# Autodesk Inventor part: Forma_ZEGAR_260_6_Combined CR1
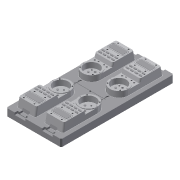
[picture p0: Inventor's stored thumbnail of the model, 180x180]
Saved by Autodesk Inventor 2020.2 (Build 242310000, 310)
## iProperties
Created: 2015-01
Part Number: Forma_ZEGAR_260_6_Combined CR1
Material: Ogólny
Document SubType Name: Modeling
Designer: F.Stasiak
Density: 1 g/cm^3
Appearance: Domyślna
Mass: 1377.71 g
Surface Area: 1826.06 cm^2
Volume: 1377.71 cm^3
Catalog Web Link: www.expertbooks.pl
Manager: www.cadconsulting.pl
Company: Fabian Stasiak CAD Consulting
Author: F.Stasiak
Subject: Zbiór ćwiczeń. Autodesk Inventor 2020. Kurs Professional
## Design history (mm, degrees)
node "Forma_ZEGAR_260_4_AsmContainer" dims "d0" = 10
sketch "Szkic1"
  geometry: L1 (0, 320)-(156, 320) reference; L2 (156, 320)-(156, 0) reference; L3 (156, 0)-(0, 0) reference; L4 (0, 0)-(0, 320) reference; L5 (0, 320)-(156, 320) reference; L6 (156, 320)-(156, 0) reference; L7 (156, 0)-(0, 0) reference; L8 (0, 0)-(0, 320) reference; L9 (0, 320)-(156, 320) reference; L10 (156, 320)-(156, 0) reference; L11 (156, 0)-(0, 0) reference; L12 (0, 0)-(0, 320) reference; L13 (0, 320)-(156, 320) reference; L14 (156, 320)-(156, 0) reference; L15 (156, 0)-(0, 0) reference; L16 (0, 0)-(0, 320) reference; L17 (156, 320)-(0, 320); L18 (0, 320)-(0, 0); L19 (0, 0)-(156, 0); L20 (156, 0)-(156, 320)
  constraints: 8 end point, 2 parallel, 1 horizontal, 1 perpendicular
sketch "Szkic2"
  geometry: L1 (78, 160)-(-78, 160) reference; L2 (-78, 160)-(-78, -160) reference; L3 (-78, -160)-(78, -160) reference; L4 (78, -160)-(78, 160) reference
sketch "Szkic3"
  geometry: L1 (78, 160)-(-78, 160) reference; L2 (-78, 160)-(-78, -160) reference; L3 (-78, -160)-(78, -160) reference; L4 (78, -160)-(78, 160) reference
sketch "Szkic4"
  geometry: L1 (78, 160)-(-78, 160) reference; L2 (-78, 160)-(-78, -160) reference; L3 (-78, -160)-(78, -160) reference; L4 (78, -160)-(78, 160) reference
sketch "Szkic5"
  geometry: L1 (78, 160)-(-78, 160) reference; L2 (-78, 160)-(-78, -160) reference; L3 (-78, -160)-(78, -160) reference; L4 (78, -160)-(78, 160) reference
chamfer "Faza1" distance "d1" = 3; stored, may be unused: second distance "d2" = 3, angle "d3" = 45 deg
chamfer "Faza2" distance "d4" = 3; stored, may be unused: second distance "d5" = 3, angle "d6" = 45 deg
chamfer "Faza3" distance "d7" = 3; stored, may be unused: second distance "d8" = 3, angle "d9" = 45 deg
chamfer "Faza4" distance "d10" = 3; stored, may be unused: second distance "d11" = 3, angle "d12" = 45 deg
sketch "Szkic6"
  geometry: 1 further point
hole "Otwór1" sketch "Szkic6" at (75, 160) diameter "d13" = 3.5; stored, may be unused: countersink angle "d17" = 90 deg, drill point angle "d19" = 0 deg; dims "d14" = 6, "d15" = 4, "d16" = 2, "d18" = 8
sketch "Szkic7"
  geometry: 1 further point
hole "Otwór2" sketch "Szkic7" at (21, 294) diameter "d20" = 4; stored, may be unused: countersink angle "d24" = 90 deg, drill point angle "d26" = 0 deg; dims "d21" = 6, "d22" = 4, "d23" = 2, "d25" = 8
feature "Rzeźbienie1"
sketch "Szkic8"
  geometry: 1 further point
hole "Otwór3" sketch "Szkic8" at (51, 294) diameter "d27" = 4; stored, may be unused: countersink angle "d31" = 90 deg, drill point angle "d33" = 0 deg; dims "d28" = 6, "d29" = 4, "d30" = 2, "d32" = 8
feature "Rzeźbienie2"
sketch "Szkic9"
  geometry: 1 further point
hole "Otwór4" sketch "Szkic9" at (21, 263.5) diameter "d34" = 4; stored, may be unused: countersink angle "d38" = 90 deg, drill point angle "d40" = 0 deg; dims "d35" = 6, "d36" = 4, "d37" = 2, "d39" = 8
feature "Rzeźbienie3"
sketch "Szkic10"
  geometry: 1 further point
hole "Otwór5" sketch "Szkic10" at (51, 263.5) diameter "d41" = 4; stored, may be unused: countersink angle "d45" = 90 deg, drill point angle "d47" = 0 deg; dims "d42" = 6, "d43" = 4, "d44" = 2, "d46" = 8
feature "Rzeźbienie4"
sketch "Szkic11"
  geometry: 1 further point
hole "Otwór6" sketch "Szkic11" at (28, 231.2) diameter "d48" = 4; stored, may be unused: countersink angle "d52" = 90 deg, drill point angle "d54" = 0 deg; dims "d49" = 6, "d50" = 4, "d51" = 2, "d53" = 8
feature "Rzeźbienie5"
sketch "Szkic12"
  geometry: 1 further point
hole "Otwór7" sketch "Szkic12" at (44, 231.2) diameter "d55" = 4; stored, may be unused: countersink angle "d59" = 90 deg, drill point angle "d61" = 0 deg; dims "d56" = 6, "d57" = 4, "d58" = 2, "d60" = 8
feature "Rzeźbienie6"
sketch "Szkic13"
  geometry: 1 further point
hole "Otwór8" sketch "Szkic13" at (26.5, 214) diameter "d62" = 4; stored, may be unused: countersink angle "d66" = 90 deg, drill point angle "d68" = 0 deg; dims "d63" = 6, "d64" = 4, "d65" = 2, "d67" = 8
feature "Rzeźbienie7"
sketch "Szkic14"
  geometry: 1 further point
hole "Otwór9" sketch "Szkic14" at (45.5, 214) diameter "d69" = 4; stored, may be unused: countersink angle "d73" = 90 deg, drill point angle "d75" = 0 deg; dims "d70" = 6, "d71" = 4, "d72" = 2, "d74" = 8
feature "Rzeźbienie8"
sketch "Szkic15"
  geometry: 1 further point
hole "Otwór10" sketch "Szkic15" at (18, 189) diameter "d76" = 4; stored, may be unused: countersink angle "d80" = 90 deg, drill point angle "d82" = 0 deg; dims "d77" = 6, "d78" = 4, "d79" = 2, "d81" = 8
feature "Rzeźbienie9"
sketch "Szkic16"
  geometry: 1 further point
hole "Otwór11" sketch "Szkic16" at (36, 195) diameter "d83" = 4; stored, may be unused: countersink angle "d87" = 90 deg, drill point angle "d89" = 0 deg; dims "d84" = 6, "d85" = 4, "d86" = 2, "d88" = 8
feature "Rzeźbienie10"
sketch "Szkic17"
  geometry: 1 further point
hole "Otwór12" sketch "Szkic17" at (54, 189) diameter "d90" = 4; stored, may be unused: countersink angle "d94" = 90 deg, drill point angle "d96" = 0 deg; dims "d91" = 6, "d92" = 4, "d93" = 2, "d95" = 8
feature "Rzeźbienie11"
feature "Rzeźbienie12"
node "Bryła1"
node "Forma_ZEGAR_260_4_ZEGAR_260_CR_1:1" dims "d0" = 10
node "Forma_ZEGAR_260_4_ZEGAR_260_CR_2:1" dims "d0" = 10
node "Forma_ZEGAR_260_4_ZEGAR_260_CR_3:1" dims "d0" = 10
node "Forma_ZEGAR_260_4_ZEGAR_260_CR_4:1" dims "d0" = 10
feature "Powierzchnia1"
body "Srf1"
feature "Powierzchnia2"
body "Srf2"
feature "Powierzchnia3"
body "Srf3"
feature "Powierzchnia4"
body "Srf4"
feature "Powierzchnia5"
body "Srf5"
feature "Powierzchnia6"
body "Srf6"
feature "Powierzchnia7"
body "Srf7"
feature "Powierzchnia8"
body "Srf8"
feature "Powierzchnia9"
body "Srf9"
feature "Powierzchnia10"
body "Srf10"
feature "Powierzchnia11"
body "Srf11"
feature "Powierzchnia12"
body "Srf12"
feature "Powierzchnia13"
body "Srf13"
feature "Powierzchnia14"
body "Srf14"
feature "Powierzchnia15"
body "Srf15"
feature "Powierzchnia16"
body "Srf16"
feature "Powierzchnia17"
body "Srf17"
feature "Powierzchnia18"
body "Srf18"
feature "Powierzchnia19"
body "Srf19"
feature "Powierzchnia20"
body "Srf20"
feature "Powierzchnia21"
body "Srf21"
feature "Powierzchnia22"
body "Srf22"
feature "Powierzchnia23"
body "Srf23"
feature "Powierzchnia24"
body "Srf24"
feature "Powierzchnia25"
body "Srf25"
feature "Powierzchnia26"
body "Srf26"
feature "Powierzchnia27"
body "Srf27"
feature "Powierzchnia28"
body "Srf28"
feature "Powierzchnia29"
body "Srf29"
feature "Powierzchnia30"
body "Srf30"
feature "Powierzchnia31"
body "Srf31"
feature "Powierzchnia32"
body "Srf32"
feature "Powierzchnia33"
body "Srf33"
feature "Powierzchnia34"
body "Srf34"
